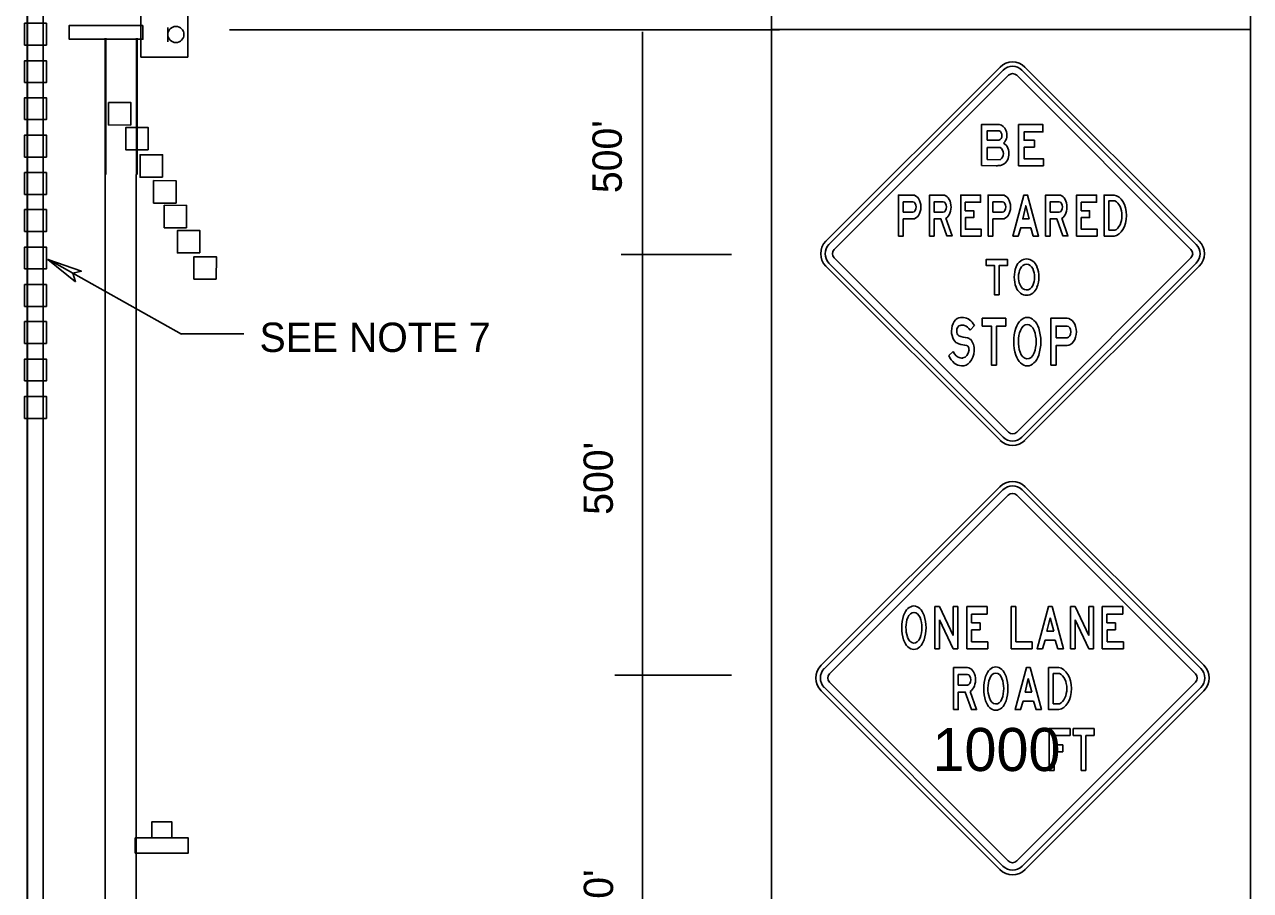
# Model space of a CAD drawing. Extents: x 21.7 to 29.1, y 5.9 to 16.2.
# Drawn here: x 24.887 to 27.394, y 9.433 to 11.205 of the extents above; entities that cross this region are included whole.
import ezdxf

# ---------------------------------------------------------------- set-up
doc = ezdxf.new("R2010")
doc.units = 0
for name, color, linetype in [('C-SIGN-FACE-N', 7, 'Continuous'), ('DETL-DIMS', 7, 'Continuous'), ('DETL-LINE', 7, 'Continuous'), ('DETL-NOTE', 7, 'Continuous')]:
    doc.layers.add(name, color=color, linetype=linetype)

msp = doc.modelspace()

# ---------------------------------------------------------------- linework, layer by layer
at = {"layer": 'C-SIGN-FACE-N'}
for p, q in [((26.8823, 11.1177), (26.5259, 10.7614)), ((26.8887, 11.1114), (26.5323, 10.755)), ((27.2833, 10.755), (26.9269, 11.1114)), ((27.2896, 10.7614), (26.9332, 11.1177)), ((26.8993, 11.1008), (26.5429, 10.7444)), ((27.2727, 10.7444), (26.9163, 11.1008)), ((26.8799, 10.9682), (26.8799, 10.9682)), ((26.8826, 10.9282), (26.8826, 10.9282)), ((26.8823, 10.3541), (26.5259, 10.7105)), ((26.8887, 10.3604), (26.5323, 10.7168)), ((26.8993, 10.371), (26.5429, 10.7274)), ((27.2896, 10.7105), (26.9332, 10.3541)), ((26.8212, 10.5794), (26.8297, 10.589)), ((26.7862, 10.5361), (26.7772, 10.5275)), ((26.9232, 10.5346), (26.9231, 10.5348)), ((26.8817, 10.2592), (26.5163, 9.8939)), ((27.2992, 9.8939), (26.9339, 10.2592)), ((26.7587, 10.0139), (26.749, 10.0139)), ((26.749, 10.0139), (26.749, 9.9278)), ((26.7864, 9.9547), (26.7587, 10.0139)), ((26.7961, 10.0139), (26.7864, 10.0139)), ((26.7864, 10.0139), (26.7864, 9.9547)), ((26.7961, 9.9278), (26.7961, 10.0139)), ((26.8142, 10.0139), (26.856, 10.0139)), ((26.8142, 9.9278), (26.8142, 10.0139)), ((26.856, 10.0139), (26.856, 9.9986)), ((26.905, 10.0139), (26.9144, 10.0139)), ((26.905, 9.9278), (26.905, 10.0139)), ((26.9144, 10.0139), (26.9144, 9.9417)), ((27.0359, 10.0139), (27.0262, 10.0139)), ((27.0262, 10.0139), (27.0262, 9.9278)), ((27.0636, 9.9547), (27.0359, 10.0139)), ((27.0733, 10.0139), (27.0636, 10.0139)), ((27.0636, 10.0139), (27.0636, 9.9547)), ((27.0733, 9.9278), (27.0733, 10.0139)), ((27.0914, 10.0139), (27.1332, 10.0139)), ((27.0914, 9.9278), (27.0914, 10.0139)), ((27.1332, 10.0139), (27.1332, 9.9986)), ((26.7587, 9.9278), (26.7587, 9.987)), ((26.7587, 9.987), (26.7864, 9.9278)), ((26.856, 9.9986), (26.8237, 9.9986)), ((26.8237, 9.9986), (26.8237, 9.9809)), ((26.8237, 9.9809), (26.8415, 9.9809)), ((26.8415, 9.9809), (26.8415, 9.9666)), ((26.9782, 9.9637), (26.9848, 9.9912)), ((26.9848, 9.9912), (26.9921, 9.9637)), ((27.0359, 9.9278), (27.0359, 9.987)), ((27.0359, 9.987), (27.0636, 9.9278)), ((27.1332, 9.9986), (27.1009, 9.9986)), ((27.1009, 9.9986), (27.1009, 9.9809)), ((27.1009, 9.9809), (27.1187, 9.9809)), ((27.1187, 9.9809), (27.1187, 9.9666)), ((26.8415, 9.9666), (26.824, 9.9666)), ((26.824, 9.9666), (26.824, 9.9421)), ((26.9921, 9.9637), (26.9782, 9.9637)), ((27.1187, 9.9666), (27.1012, 9.9666)), ((27.1012, 9.9666), (27.1012, 9.9421)), ((26.824, 9.9421), (26.8573, 9.9421)), ((26.8573, 9.9421), (26.8573, 9.9278)), ((26.9144, 9.9417), (26.9481, 9.9417)), ((26.9481, 9.9417), (26.9481, 9.9278)), ((26.9952, 9.9451), (26.9953, 9.9451)), ((26.9952, 9.9451), (26.9953, 9.9451)), ((27.1012, 9.9421), (27.1345, 9.9421)), ((27.1345, 9.9421), (27.1345, 9.9278)), ((26.749, 9.9278), (26.7587, 9.9278)), ((26.7864, 9.9278), (26.7961, 9.9278)), ((26.8573, 9.9278), (26.8142, 9.9278)), ((26.9481, 9.9278), (26.905, 9.9278)), ((27.0262, 9.9278), (27.0359, 9.9278)), ((27.0636, 9.9278), (27.0733, 9.9278)), ((27.1345, 9.9278), (27.0914, 9.9278)), ((26.9334, 9.8391), (26.94, 9.8666)), ((26.94, 9.8666), (26.9473, 9.8391)), ((26.8817, 9.4763), (26.5163, 9.8417)), ((26.9473, 9.8391), (26.9334, 9.8391)), ((27.2992, 9.8417), (26.9339, 9.4763)), ((26.9504, 9.8205), (26.9505, 9.8205)), ((26.9504, 9.8205), (26.9505, 9.8205)), ((26.9827, 9.7647), (27.0257, 9.7647)), ((26.9827, 9.6786), (26.9827, 9.7647)), ((27.0257, 9.7647), (27.0257, 9.7501)), ((27.0316, 9.7647), (27.0746, 9.7647)), ((27.0746, 9.7647), (27.0316, 9.7647)), ((27.0746, 9.7647), (27.0316, 9.7647)), ((27.0316, 9.7647), (27.0316, 9.7504)), ((27.0746, 9.7504), (27.0746, 9.7647)), ((27.0257, 9.7501), (26.9926, 9.7501)), ((26.9926, 9.7501), (26.9926, 9.7311)), ((26.9926, 9.7311), (27.0105, 9.7311)), ((27.0105, 9.7311), (27.0105, 9.717)), ((27.0316, 9.7504), (27.0483, 9.7504)), ((27.0483, 9.7504), (27.0483, 9.6786)), ((27.0579, 9.6786), (27.0579, 9.7504)), ((27.0579, 9.7504), (27.0746, 9.7504)), ((27.0105, 9.717), (26.9926, 9.717)), ((26.9926, 9.717), (26.9926, 9.6786)), ((26.9926, 9.6786), (26.9827, 9.6786)), ((27.0483, 9.6786), (27.0579, 9.6786))]:
    msp.add_line(p, q, dxfattribs=at)
for points in [[(26.8887, 11.1114), (26.5323, 10.755)], [(27.2833, 10.755), (26.9269, 11.1114)], [(26.5429, 10.7444), (26.8993, 11.1008)], [(26.9163, 11.1008), (27.2727, 10.7444)], [(26.8807, 10.9999), (26.8441, 10.9999), (26.8441, 10.916)], [(26.8799, 10.9682), (26.856, 10.9682), (26.856, 10.9872), (26.8807, 10.9872)], [(26.856, 10.9283), (26.856, 10.953), (26.8825, 10.9529)], [(26.8441, 10.916), (26.8741, 10.9159)], [(26.8826, 10.9282), (26.856, 10.9283)], [(26.7037, 10.8559), (26.6843, 10.8559), (26.6745, 10.8559), (26.6745, 10.7719)], [(26.7037, 10.8209), (26.6843, 10.8209), (26.6843, 10.8419), (26.7037, 10.8419)], [(26.766, 10.8559), (26.7474, 10.8559), (26.7382, 10.8559), (26.7382, 10.7719)], [(26.766, 10.8209), (26.7474, 10.8209), (26.7474, 10.8419), (26.766, 10.8419)], [(26.8871, 10.8559), (26.8677, 10.8559), (26.8579, 10.8559), (26.8579, 10.7719)], [(26.8871, 10.8209), (26.8677, 10.8209), (26.8677, 10.8419), (26.8871, 10.8419)], [(27.0031, 10.8559), (26.9846, 10.8559), (26.9753, 10.8559), (26.9753, 10.7719)], [(26.9846, 10.8209), (26.9846, 10.8419), (27.0031, 10.8419)], [(27.1155, 10.8559), (27.0951, 10.8559), (27.0951, 10.7719)], [(27.1045, 10.7838), (27.1045, 10.844), (27.1169, 10.844)], [(26.7382, 10.7719), (26.7474, 10.7719), (26.7474, 10.8069), (26.7613, 10.8069), (26.7736, 10.7721), (26.7841, 10.7721), (26.7713, 10.8083)], [(26.9753, 10.7719), (26.9846, 10.7719), (26.9846, 10.8069), (26.9985, 10.8069), (27.0108, 10.7721), (27.0212, 10.7721), (27.0084, 10.8083)], [(27.0031, 10.8209), (26.9846, 10.8209)], [(26.6745, 10.7719), (26.6843, 10.7719), (26.6843, 10.8069), (26.7037, 10.8069)], [(26.8579, 10.7719), (26.8677, 10.7719), (26.8677, 10.8069), (26.8871, 10.8069)], [(27.1169, 10.7838), (27.1045, 10.7838)], [(27.0951, 10.7719), (27.1155, 10.7719)], [(26.5323, 10.7168), (26.8887, 10.3604)], [(26.8993, 10.371), (26.5429, 10.7274), (26.5429, 10.7274)], [(27.2727, 10.7274), (26.9464, 10.4011), (26.9163, 10.371)], [(26.9269, 10.3604), (27.2833, 10.7168)], [(27.0192, 10.6039), (26.997, 10.6039), (26.9859, 10.6039), (26.9859, 10.5079)], [(26.997, 10.5639), (26.997, 10.5879), (27.0192, 10.5879)], [(27.0192, 10.5639), (26.997, 10.5639)], [(26.9859, 10.5079), (26.997, 10.5079), (26.997, 10.5479), (27.0192, 10.5479)], [(26.8882, 10.2527), (26.5229, 9.8874)], [(26.5337, 9.8765), (26.8991, 10.2418)], [(26.9165, 10.2418), (27.2818, 9.8765)], [(27.2927, 9.8874), (26.9274, 10.2527)], [(26.9953, 9.9451), (26.9743, 9.9451), (26.969, 9.9278), (26.9579, 9.9278), (26.981, 10.0139), (26.9885, 10.0139), (27.0117, 9.9278), (27.0006, 9.9278), (26.9952, 9.9451)], [(26.7871, 9.8032), (26.7871, 9.8893), (26.7966, 9.8893), (26.8156, 9.8893)], [(26.9505, 9.8205), (26.9295, 9.8205), (26.9241, 9.8032), (26.913, 9.8032), (26.9362, 9.8893), (26.9437, 9.8893), (26.9669, 9.8032), (26.9558, 9.8032), (26.9504, 9.8205)], [(27.0023, 9.8032), (26.9814, 9.8032), (26.9814, 9.8893), (27.0023, 9.8893)], [(26.8991, 9.4937), (26.5337, 9.8591)], [(26.8156, 9.8534), (26.7966, 9.8534), (26.7966, 9.8749), (26.8156, 9.8749)], [(27.2818, 9.8591), (26.9165, 9.4937)], [(27.0038, 9.8771), (26.9911, 9.8771), (26.9911, 9.8154), (27.0038, 9.8154)], [(26.5229, 9.8482), (26.8882, 9.4829)], [(26.821, 9.8405), (26.8342, 9.8033), (26.8235, 9.8033), (26.8109, 9.839), (26.7966, 9.839), (26.7966, 9.8032), (26.7871, 9.8032)], [(26.9274, 9.4829), (27.2927, 9.8482)]]:
    msp.add_lwpolyline(points, dxfattribs=at)
for points in [[(26.9714, 10.9159), (26.9714, 10.9299), (26.9318, 10.9299), (26.9318, 10.9538), (26.9526, 10.9538), (26.9526, 10.9678), (26.9315, 10.9678), (26.9315, 10.985), (26.9699, 10.985), (26.9699, 10.9999), (26.9203, 10.9999), (26.9203, 10.9159)], [(26.8438, 10.7719), (26.8438, 10.7859), (26.8113, 10.7859), (26.8113, 10.8098), (26.8283, 10.8098), (26.8283, 10.8238), (26.811, 10.8238), (26.811, 10.841), (26.8425, 10.841), (26.8425, 10.8559), (26.8018, 10.8559), (26.8018, 10.7719)], [(26.9451, 10.7888), (26.9503, 10.7719), (26.9611, 10.7719), (26.9385, 10.8559), (26.9312, 10.8559), (26.9086, 10.7719), (26.9195, 10.7719), (26.9247, 10.7888)], [(26.9421, 10.807), (26.9285, 10.807), (26.9349, 10.8338)], [(27.0809, 10.7719), (27.0809, 10.7859), (27.0484, 10.7859), (27.0484, 10.8098), (27.0655, 10.8098), (27.0655, 10.8238), (27.0482, 10.8238), (27.0482, 10.841), (27.0797, 10.841), (27.0797, 10.8559), (27.0389, 10.8559), (27.0389, 10.7719)], [(26.8806, 10.6519), (26.8708, 10.6519), (26.8708, 10.7119), (26.8538, 10.7119), (26.8538, 10.7239), (26.8976, 10.7239), (26.8976, 10.7119), (26.8806, 10.7119)], [(26.8753, 10.5079), (26.8646, 10.5079), (26.8646, 10.5879), (26.8459, 10.5879), (26.8459, 10.6039), (26.8939, 10.6039), (26.8939, 10.5879), (26.8753, 10.5879)]]:
    msp.add_lwpolyline(points, close=True, dxfattribs=at)
for centre, radius, start, end in [((26.9078, 11.0923), 0.036, 45, 135), ((26.9078, 11.0923), 0.027, 45, 135), ((26.9078, 11.0923), 0.027, 45, 135), ((26.9078, 11.0923), 0.012, 45, 135), ((26.9078, 11.0923), 0.012, 45, 135), ((26.5514, 10.7359), 0.036, 135, 225), ((27.2642, 10.7359), 0.036, 315, 45), ((26.5514, 10.7359), 0.027, 135, 225), ((26.5514, 10.7359), 0.027, 135, 225), ((26.5514, 10.7359), 0.012, 135, 224.9596), ((26.5514, 10.7359), 0.012, 135, 224.9596), ((27.2642, 10.7359), 0.012, 315, 45), ((27.2642, 10.7359), 0.012, 315, 45), ((27.2642, 10.7359), 0.027, 315, 45), ((27.2642, 10.7359), 0.027, 315, 45), ((26.9078, 10.3795), 0.027, 225, 315), ((26.9078, 10.3795), 0.027, 225, 315), ((26.9078, 10.3795), 0.012, 225, 315), ((26.9078, 10.3795), 0.012, 225, 315), ((26.9078, 10.3795), 0.036, 225, 315), ((26.9078, 10.2331), 0.0369, 45, 135), ((26.9078, 10.2331), 0.0277, 45, 135), ((26.9078, 10.2331), 0.0123, 45, 135), ((26.5424, 9.8678), 0.0369, 135, 225), ((26.5424, 9.8678), 0.0277, 135, 225), ((27.2731, 9.8678), 0.0277, 315, 45), ((27.2731, 9.8678), 0.0369, 315, 45), ((26.5424, 9.8678), 0.0123, 135, 225), ((27.2731, 9.8678), 0.0123, 315, 45), ((26.9078, 9.5024), 0.0277, 225, 315), ((26.9078, 9.5024), 0.0123, 225, 315), ((26.9078, 9.5024), 0.0369, 225, 315)]:
    msp.add_arc(centre, radius, start, end, dxfattribs=at)
for centre, major_axis, ratio, start_param, end_param in [((26.8778, 10.9779), (0, 0.00997), 0.839466, 3.388797, 5.931995), ((26.8784, 10.9789), (0, 0.0211), 0.839466, 5.185175, 6.153935), ((26.8792, 10.9785), (0, 0.0205), 0.839466, 3.776083, 5.22325), ((26.8803, 10.9405), (0, 0.0241), 0.839466, 3.374344, 5.817162), ((26.8777, 10.9405), (0, 0.0136), 0.839466, 3.582433, 5.852916), ((26.8746, 10.9587), (0, 0.0428), 0.839466, 3.125363, 3.212577), ((26.8731, 11.0077), (0, 0.0919), 0.839466, 3.195342, 3.296884), ((26.7035, 10.8314), (0, 0.0245), 0.693489, 3.155423, 6.269038), ((26.7035, 10.8314), (0, 0.0105), 0.693489, 3.174143, 6.249901), ((26.7658, 10.8314), (0, 0.0245), 0.661997, 3.487455, 6.269173), ((26.7658, 10.8314), (0, 0.0105), 0.661997, 3.174143, 6.250249), ((26.8869, 10.8314), (0, 0.0245), 0.693489, 3.155423, 6.269132), ((26.8869, 10.8314), (0, 0.0105), 0.693489, 3.174143, 6.25012), ((27.0029, 10.8314), (0, 0.0245), 0.661997, 3.487757, 6.26934), ((27.0029, 10.8314), (0, 0.0105), 0.661997, 3.174143, 6.250635), ((27.1129, 10.8139), (0, 0.0422), 0.666086, 3.232672, 6.192098), ((27.1106, 10.8139), (0, 0.0316), 0.666086, 3.446507, 5.978172), ((26.9485, 10.6879), (0, 0.0459), 0.812335, 1.101522, 2.04007), ((26.9365, 10.6959), (0, 0.0292), 0.812335, 5.167056, 7.399315), ((26.9365, 10.6959), (0, 0.0183), 0.812335, 5.251232, 7.315139), ((26.9245, 10.6879), (0, 0.0459), 0.812335, 4.243115, 5.181663), ((26.9485, 10.6879), (0, 0.0351), 0.812335, 1.053076, 2.040122), ((26.9245, 10.6879), (0, 0.0351), 0.812335, 4.194619, 5.230159), ((26.9365, 10.68), (0, 0.0292), 0.812335, 2.025463, 3.141593), ((26.9365, 10.68), (0, 0.0183), 0.812335, 2.025521, 3.099563), ((26.9365, 10.68), (0, 0.0183), 0.812335, 3.099563, 4.173604), ((26.9365, 10.68), (0, 0.0292), 0.812335, 3.141593, 4.257722), ((26.8013, 10.5776), (0, 0.0276), 0.66615, 6.26385, 7.849768), ((26.8013, 10.5776), (0, 0.0116), 0.66615, 0.077411, 1.57362), ((26.8046, 10.5543), (0, 0.0353), 0.66615, 6.063078, 6.446889), ((26.8046, 10.5606), (0, 0.0448), 0.66615, 6.185083, 6.379154), ((26.8063, 10.5592), (0, 0.0461), 0.66615, 5.417783, 6.245524), ((26.8063, 10.5592), (0, 0.0301), 0.66615, 5.451674, 6.113321), ((26.951, 10.5559), (0, 0.0612), 0.667963, 1.101522, 2.04007), ((26.9379, 10.5665), (0, 0.0389), 0.667963, 5.167056, 7.399315), ((26.9379, 10.5665), (0, 0.0245), 0.667963, 5.251232, 7.315139), ((26.9248, 10.5559), (0, 0.0612), 0.667963, 4.243115, 5.181663), ((27.0189, 10.5759), (0, 0.028), 0.693489, 3.155423, 6.268798), ((27.0189, 10.5759), (0, 0.012), 0.693489, 3.174143, 6.250635), ((26.8003, 10.5774), (0, 0.026), 0.66615, 1.5566, 3.019028), ((26.8003, 10.5774), (0, 0.01), 0.66615, 1.548818, 2.74578), ((26.8276, 10.7526), (0, 0.1898), 0.66615, 2.903022, 3.048485), ((26.8094, 10.5178), (0, 0.0467), 0.66615, 5.858321, 6.074573), ((26.8118, 10.539), (0, 0.0265), 0.66615, 4.646351, 5.651125), ((26.951, 10.5559), (0, 0.0468), 0.667963, 1.053076, 2.040122), ((26.9248, 10.5559), (0, 0.0468), 0.667963, 4.194619, 5.230159), ((26.8035, 10.5541), (0, 0.0315), 0.66615, 2.178648, 3.018166), ((26.8276, 10.7526), (0, 0.2058), 0.66615, 2.925313, 3.043429), ((26.8056, 10.5427), (0, 0.0362), 0.66615, 3.054011, 4.562492), ((26.8056, 10.5427), (0, 0.0202), 0.66615, 3.202031, 4.526443), ((26.8094, 10.5178), (0, 0.0307), 0.66615, 5.919654, 6.048202), ((26.8118, 10.539), (0, 0.0105), 0.66615, 4.704762, 5.511974), ((26.9379, 10.5453), (0, 0.0245), 0.667963, 2.025521, 4.173604), ((26.8035, 10.5541), (0, 0.0475), 0.66615, 2.164837, 3.141505), ((26.8047, 10.5623), (0, 0.0399), 0.66615, 2.996497, 3.204075), ((26.9379, 10.5453), (0, 0.0389), 0.667963, 2.025463, 3.141593), ((26.9379, 10.5453), (0, 0.0389), 0.667963, 3.141593, 4.257722), ((26.706, 9.9803), (0, 0.0349), 0.667963, 5.167056, 7.399315), ((26.7178, 9.9708), (0, 0.0549), 0.667963, 1.101522, 2.04007), ((26.7178, 9.9708), (0, 0.042), 0.667963, 1.053076, 2.040122), ((26.706, 9.9803), (0, 0.0219), 0.667963, 5.251232, 7.315139), ((26.6942, 9.9708), (0, 0.042), 0.667963, 4.194619, 5.230159), ((26.6942, 9.9708), (0, 0.0549), 0.667963, 4.243115, 5.181663), ((26.706, 9.9613), (0, 0.0349), 0.667963, 2.025463, 4.257722), ((26.706, 9.9613), (0, 0.0219), 0.667963, 2.025521, 4.173604), ((26.8154, 9.8642), (0, 0.0251), 0.661997, 3.487455, 6.26934), ((26.8736, 9.8557), (0, 0.0349), 0.667963, 5.167056, 7.399315), ((26.9997, 9.8462), (0, 0.0432), 0.666086, 3.232672, 6.192106), ((26.8154, 9.8642), (0, 0.0108), 0.661997, 3.174143, 6.250635), ((26.8854, 9.8462), (0, 0.0549), 0.667963, 1.101522, 2.04007), ((26.8854, 9.8462), (0, 0.042), 0.667963, 1.053076, 2.040122), ((26.8736, 9.8558), (0, 0.0219), 0.667963, 5.251232, 7.315139), ((26.8618, 9.8462), (0, 0.042), 0.667963, 4.194619, 5.230159), ((26.8618, 9.8462), (0, 0.0549), 0.667963, 4.243115, 5.181663), ((26.9973, 9.8462), (0, 0.0324), 0.666086, 3.446507, 5.978271), ((26.8736, 9.8367), (0, 0.0349), 0.667963, 2.025463, 4.257722), ((26.8736, 9.8367), (0, 0.0219), 0.667963, 2.025521, 4.173604)]:
    msp.add_ellipse(centre, major_axis=major_axis, ratio=ratio, start_param=start_param, end_param=end_param, dxfattribs=at)
at = {"layer": 'DETL-DIMS'}
for p, q in [((26.1511, 11.1897), (26.1511, 10.7339)), ((26.107, 10.7339), (26.3328, 10.7339)), ((26.1511, 10.7339), (26.1511, 9.8738)), ((24.9349, 10.7242), (24.991, 10.6781)), ((24.9349, 10.7242), (25.0034, 10.7001)), ((25.2082, 10.5715), (24.9363, 10.7239)), ((24.9855, 10.6957), (25.0034, 10.7001)), ((24.991, 10.6781), (24.9855, 10.6957)), ((25.3357, 10.5717), (25.2075, 10.5717)), ((26.0942, 9.8738), (26.3328, 9.8738)), ((26.1511, 9.8738), (26.1511, 8.9847))]:
    msp.add_line(p, q, dxfattribs=at)
msp.add_lwpolyline([(24.991, 10.6781), (24.9349, 10.7242), (25.0034, 10.7001), (24.9855, 10.6957)], close=True, dxfattribs=at)
at = {"layer": 'DETL-LINE'}
for p, q in [((24.8927, 7.7401), (24.8927, 15.6283)), ((24.893, 9.2959), (24.893, 15.5751)), ((24.9252, 9.2959), (24.9252, 15.5751)), ((24.9252, 7.7401), (24.9252, 15.5547)), ((26.4145, 11.5089), (26.4145, 7.6665)), ((27.3944, 7.6665), (27.3944, 11.5089)), ((25.1802, 11.1985), (25.1802, 11.1691)), ((26.431, 11.1937), (25.3063, 11.1937)), ((27.3944, 11.1944), (26.4145, 11.1944)), ((25.0522, 10.8977), (25.0522, 11.1765)), ((25.0527, 10.8979), (25.0527, 11.1767)), ((25.0534, 10.8977), (25.0534, 11.1765)), ((25.116, 10.8977), (25.116, 11.1765)), ((25.1164, 10.8979), (25.1164, 11.1767)), ((25.1171, 10.8977), (25.1171, 11.1765)), ((25.0521, 9.2959), (25.0521, 10.8977)), ((25.1155, 9.2959), (25.1155, 10.8977))]:
    msp.add_line(p, q, dxfattribs=at)
for points in [[(25.1252, 11.1381), (25.1252, 11.3006), (25.2207, 11.3006), (25.2207, 11.1381)], [(24.887, 11.1626), (24.9318, 11.1626), (24.9318, 11.2074), (24.887, 11.2074)], [(25.129, 11.2027), (24.9785, 11.2027), (24.9785, 11.1745), (25.129, 11.1745)], [(24.887, 11.0859), (24.9318, 11.0859), (24.9318, 11.1307), (24.887, 11.1307)], [(24.887, 11.0102), (24.9318, 11.0102), (24.9318, 11.055), (24.887, 11.055)], [(25.1045, 10.999), (25.1046, 11.0449), (25.0588, 11.045), (25.0587, 10.9992)], [(25.1401, 10.9481), (25.1402, 10.9939), (25.0943, 10.9941), (25.0943, 10.9483)], [(24.887, 10.9336), (24.9318, 10.9336), (24.9318, 10.9784), (24.887, 10.9784)], [(25.1692, 10.8922), (25.1693, 10.9381), (25.1235, 10.9382), (25.1234, 10.8924)], [(24.887, 10.857), (24.9318, 10.857), (24.9318, 10.9018), (24.887, 10.9018)], [(25.1968, 10.8393), (25.197, 10.8852), (25.1511, 10.8853), (25.1511, 10.8395)], [(25.2185, 10.7887), (25.2186, 10.8346), (25.1727, 10.8348), (25.1727, 10.7889)], [(24.887, 10.7812), (24.9318, 10.7812), (24.9318, 10.826), (24.887, 10.826)], [(25.2455, 10.7373), (25.2456, 10.7832), (25.1998, 10.7833), (25.1997, 10.7375)], [(24.887, 10.7046), (24.9318, 10.7046), (24.9318, 10.7494), (24.887, 10.7494)], [(25.2792, 10.6836), (25.2794, 10.7295), (25.2335, 10.7296), (25.2334, 10.6838)], [(24.887, 10.628), (24.9318, 10.628), (24.9318, 10.6728), (24.887, 10.6728)], [(24.887, 10.5523), (24.9318, 10.5523), (24.9318, 10.5971), (24.887, 10.5971)], [(24.887, 10.4756), (24.9318, 10.4756), (24.9318, 10.5204), (24.887, 10.5204)], [(24.887, 10.399), (24.9318, 10.399), (24.9318, 10.4438), (24.887, 10.4438)], [(25.1471, 9.5408), (25.1884, 9.5408), (25.1884, 9.5735), (25.1471, 9.5735)], [(25.1135, 9.5408), (25.1135, 9.5099), (25.2217, 9.5099), (25.2217, 9.5408)]]:
    msp.add_lwpolyline(points, close=True, dxfattribs=at)
msp.add_circle((25.1966, 11.1843), 0.0165, dxfattribs=at)

# ---------------------------------------------------------------- texts
at = {"layer": 'DETL-NOTE'}
for p in [(26.1086, 10.8597), (26.0903, 10.2017), (26.0908, 9.3271)]:
    msp.add_text("500'", height=0.06, rotation=90, dxfattribs=at).set_placement(p)
for s, height, p in [('SEE NOTE 7', 0.06, (25.3677, 10.5349)), ('1000', 0.088, (26.744, 9.6777))]:
    msp.add_text(s, height=height, dxfattribs=at).set_placement(p)

doc.saveas('drawing.dxf')
